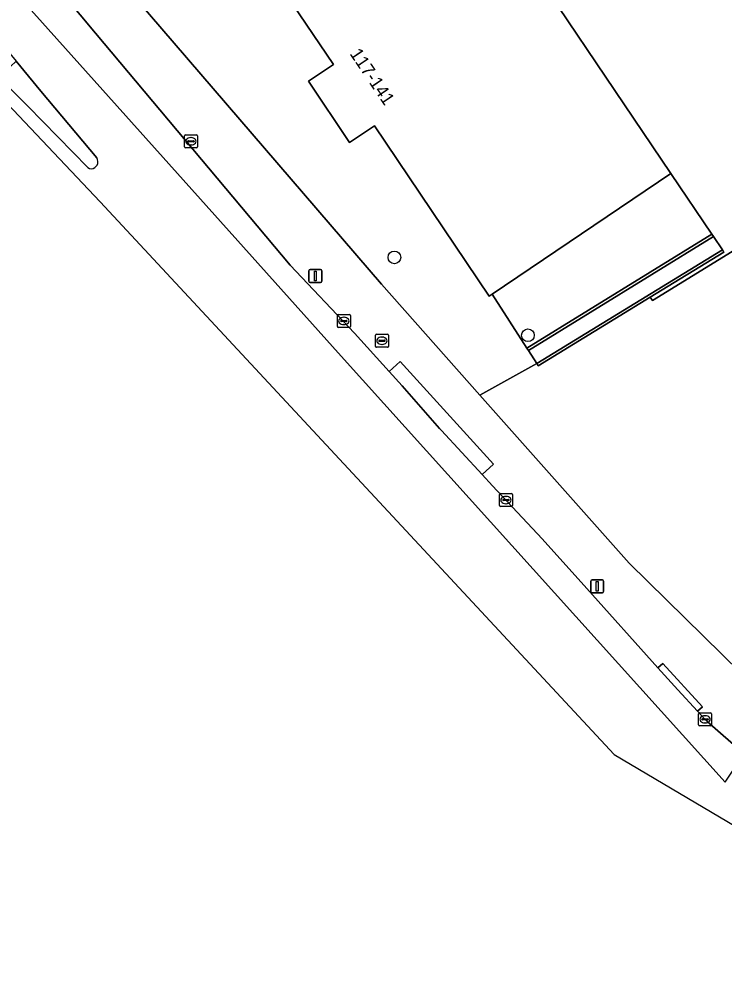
# Model space of a CAD drawing. Extents: x 161087 to 161926, y 382572 to 383873.
# Drawn here: x 161655.3 to 161709.7, y 382571.9 to 382644.9 of the extents above; entities that cross this region are included whole.
import ezdxf

# ---------------------------------------------------------------- set-up
doc = ezdxf.new("R2010")
doc.units = 0
for name, color, linetype in [('IMGEO_Boom', 7, 'Continuous'), ('IMGEO_Erf', 7, 'Continuous'), ('IMGEO_Kolk', 7, 'Continuous'), ('IMGEO_Lichtmast', 7, 'Continuous'), ('IMGEO_Muur', 7, 'Continuous'), ('IMGEO_Pand', 7, 'Continuous'), ('IMGEO_Pand_nummerreeks', 7, 'Continuous'), ('IMGEO_Rijbaan_lokaal_gesloten', 7, 'Continuous'), ('IMGEO_Rijbaan_lokaal_open', 7, 'Continuous'), ('IMGEO_Rioolput', 7, 'Continuous'), ('IMGEO_Verkeerseiland_open', 7, 'Continuous'), ('IMGEO_Voetpad_open', 7, 'Continuous')]:
    doc.layers.add(name, color=color, linetype=linetype)

msp = doc.modelspace()

# ---------------------------------------------------------------- linework, layer by layer
at = {"layer": 'IMGEO_Boom'}
for centre in [(161684.288, 382626.497), (161694.582, 382620.498)]:
    msp.add_circle(centre, 0.489, dxfattribs=at)
at = {"layer": 'IMGEO_Erf'}
for points in [[(161715.388, 382659.714), (161715.213, 382659.599), (161715.065, 382659.813), (161715.235, 382659.927), (161712.849, 382663.468), (161711.028, 382662.242), (161709.203, 382664.95), (161691.894, 382653.285), (161705.616, 382632.96), (161708.777, 382628.279), (161708.895, 382628.104), (161709.59, 382627.074), (161709.708, 382626.9), (161704.022, 382623.425), (161704.187, 382623.185), (161742.576, 382646.789), (161760.971, 382658.101), (161760.61, 382659.053), (161759.351, 382662.367), (161759.169, 382662.845), (161745.752, 382698.169)], [(161779.952, 382608.946), (161767.176, 382642.388), (161760.971, 382658.101), (161742.576, 382646.789), (161704.187, 382623.185), (161704.022, 382623.425), (161695.384, 382618.145), (161695.27, 382618.322), (161690.885, 382615.891), (161702.391, 382602.921), (161711.019, 382594.472), (161714.507, 382591.277)], [(161663.329, 382647.645), (161683.298, 382624.442), (161690.885, 382615.891), (161695.27, 382618.322), (161694.625, 382619.322), (161694.511, 382619.499), (161691.82, 382623.671), (161691.596, 382623.521), (161682.748, 382636.635), (161680.826, 382635.348), (161677.646, 382640.087), (161679.583, 382641.37), (161672.727, 382651.507)]]:
    msp.add_lwpolyline(points, dxfattribs=at)
at = {"layer": 'IMGEO_Kolk'}
for p, q in [((161668.089, 382635.023), (161668.089, 382635.875)), ((161668.164, 382635.949), (161669.016, 382635.949)), ((161669.09, 382635.875), (161669.09, 382635.023)), ((161668.348, 382635.443), (161668.348, 382635.455)), ((161668.786, 382635.406), (161668.388, 382635.406)), ((161668.391, 382635.492), (161668.789, 382635.492)), ((161668.6, 382635.169), (161668.575, 382635.169)), ((161668.577, 382635.729), (161668.602, 382635.729)), ((161668.832, 382635.455), (161668.832, 382635.443)), ((161669.016, 382634.949), (161668.164, 382634.949)), ((161679.885, 382621.176), (161679.885, 382622.028)), ((161679.96, 382622.102), (161680.812, 382622.102)), ((161680.886, 382622.028), (161680.886, 382621.176)), ((161680.144, 382621.596), (161680.144, 382621.608)), ((161680.582, 382621.559), (161680.184, 382621.559)), ((161680.187, 382621.645), (161680.585, 382621.645)), ((161680.396, 382621.322), (161680.371, 382621.322)), ((161680.373, 382621.882), (161680.398, 382621.882)), ((161680.628, 382621.608), (161680.628, 382621.596)), ((161680.812, 382621.102), (161679.96, 382621.102)), ((161692.389, 382607.365), (161692.389, 382608.217)), ((161692.464, 382608.291), (161693.316, 382608.291)), ((161693.39, 382608.217), (161693.39, 382607.365)), ((161692.648, 382607.785), (161692.648, 382607.797)), ((161693.086, 382607.748), (161692.688, 382607.748)), ((161692.691, 382607.834), (161693.089, 382607.834)), ((161692.9, 382607.511), (161692.875, 382607.511)), ((161692.877, 382608.071), (161692.902, 382608.071)), ((161693.132, 382607.797), (161693.132, 382607.785)), ((161693.316, 382607.291), (161692.464, 382607.291)), ((161707.83, 382591.39), (161708.682, 382591.39)), ((161707.755, 382590.464), (161707.755, 382591.316)), ((161708.014, 382590.884), (161708.014, 382590.896)), ((161708.452, 382590.847), (161708.054, 382590.847)), ((161708.057, 382590.933), (161708.455, 382590.933)), ((161708.266, 382590.61), (161708.241, 382590.61)), ((161708.243, 382591.17), (161708.268, 382591.17)), ((161708.498, 382590.896), (161708.498, 382590.884)), ((161708.756, 382591.316), (161708.756, 382590.464)), ((161708.682, 382590.39), (161707.83, 382590.39))]:
    msp.add_line(p, q, dxfattribs=at)
for points in [[(161668.089, 382635.023), (161668.089, 382635.875)], [(161668.164, 382635.949), (161669.016, 382635.949)], [(161669.09, 382635.875), (161669.09, 382635.023)], [(161669.016, 382634.949), (161668.164, 382634.949)], [(161679.885, 382621.176), (161679.885, 382622.028)], [(161679.96, 382622.102), (161680.812, 382622.102)], [(161680.886, 382622.028), (161680.886, 382621.176)], [(161680.812, 382621.102), (161679.96, 382621.102)], [(161692.389, 382607.365), (161692.389, 382608.217)], [(161692.464, 382608.291), (161693.316, 382608.291)], [(161693.39, 382608.217), (161693.39, 382607.365)], [(161693.316, 382607.291), (161692.464, 382607.291)], [(161707.83, 382591.39), (161708.682, 382591.39)], [(161707.755, 382590.464), (161707.755, 382591.316)], [(161708.756, 382591.316), (161708.756, 382590.464)], [(161708.682, 382590.39), (161707.83, 382590.39)]]:
    msp.add_lwpolyline(points, dxfattribs=at)
for centre, radius, start, end in [((161668.166, 382635.873), 0.0765, 91.55205, 178.44795), ((161668.166, 382635.873), 0.0765, 91.55205, 178.44795), ((161669.014, 382635.873), 0.0765, 1.55205, 88.44795), ((161669.014, 382635.873), 0.0765, 1.55205, 88.44795), ((161668.388, 382635.452), 0.0403, 85.87752, 175.75265), ((161668.385, 382635.442), 0.0366, 178.93798, 274.71019), ((161668.789, 382635.449), 0.043, 264.86636, 352.45326), ((161668.793, 382635.454), 0.0386, 1.73085, 96.63898), ((161668.166, 382635.025), 0.0765, 181.55205, 268.44795), ((161668.166, 382635.025), 0.0765, 181.55205, 268.44795), ((161669.014, 382635.025), 0.0765, 271.55205, 358.44795), ((161669.014, 382635.025), 0.0765, 271.55205, 358.44795), ((161679.962, 382622.026), 0.0765, 91.55205, 178.44795), ((161679.962, 382622.026), 0.0765, 91.55205, 178.44795), ((161680.81, 382622.026), 0.0765, 1.55205, 88.44795), ((161680.81, 382622.026), 0.0765, 1.55205, 88.44795), ((161680.184, 382621.605), 0.0403, 85.87752, 175.75265), ((161680.181, 382621.595), 0.0366, 178.93798, 274.71019), ((161680.585, 382621.602), 0.043, 264.86636, 352.45326), ((161680.589, 382621.607), 0.0386, 1.73085, 96.63898), ((161679.962, 382621.178), 0.0765, 181.55205, 268.44795), ((161679.962, 382621.178), 0.0765, 181.55205, 268.44795), ((161680.81, 382621.178), 0.0765, 271.55205, 358.44795), ((161680.81, 382621.178), 0.0765, 271.55205, 358.44795), ((161692.466, 382608.215), 0.0765, 91.55205, 178.44795), ((161692.466, 382608.215), 0.0765, 91.55205, 178.44795), ((161693.314, 382608.215), 0.0765, 1.55205, 88.44795), ((161693.314, 382608.215), 0.0765, 1.55205, 88.44795), ((161692.688, 382607.794), 0.0403, 85.87752, 175.75265), ((161692.685, 382607.784), 0.0366, 178.93798, 274.71019), ((161693.089, 382607.791), 0.043, 264.86636, 352.45326), ((161693.093, 382607.796), 0.0386, 1.73085, 96.63898), ((161692.466, 382607.367), 0.0765, 181.55205, 268.44795), ((161692.466, 382607.367), 0.0765, 181.55205, 268.44795), ((161693.314, 382607.367), 0.0765, 271.55205, 358.44795), ((161693.314, 382607.367), 0.0765, 271.55205, 358.44795), ((161707.832, 382591.314), 0.0765, 91.55205, 178.44795), ((161707.832, 382591.314), 0.0765, 91.55205, 178.44795), ((161708.68, 382591.314), 0.0765, 1.55205, 88.44795), ((161708.68, 382591.314), 0.0765, 1.55205, 88.44795), ((161708.054, 382590.893), 0.0403, 85.87752, 175.75265), ((161708.051, 382590.883), 0.0366, 178.93798, 274.71019), ((161708.455, 382590.89), 0.043, 264.86636, 352.45326), ((161708.459, 382590.895), 0.0386, 1.73085, 96.63898), ((161707.832, 382590.466), 0.0765, 181.55205, 268.44795), ((161707.832, 382590.466), 0.0765, 181.55205, 268.44795), ((161708.68, 382590.466), 0.0765, 271.55205, 358.44795), ((161708.68, 382590.466), 0.0765, 271.55205, 358.44795)]:
    msp.add_arc(centre, radius, start, end, dxfattribs=at)
for centre, major_axis, ratio, start_param, end_param in [((161668.576, 382635.449), (-0.387, 0.002), 0.722429, 4.712389, 7.853982), ((161668.601, 382635.449), (-0.39, 0.002), 0.717154, 1.570796, 4.712389), ((161680.372, 382621.602), (-0.387, 0.002), 0.722429, 4.712389, 7.853982), ((161680.397, 382621.602), (-0.39, 0.002), 0.717154, 1.570796, 4.712389), ((161692.876, 382607.791), (-0.387, 0.002), 0.722429, 4.712389, 7.853982), ((161692.901, 382607.791), (-0.39, 0.002), 0.717154, 1.570796, 4.712389), ((161708.242, 382590.89), (-0.387, 0.002), 0.722429, 4.712389, 7.853982), ((161708.267, 382590.89), (-0.39, 0.002), 0.717154, 1.570796, 4.712389)]:
    msp.add_ellipse(centre, major_axis=major_axis, ratio=ratio, start_param=start_param, end_param=end_param, dxfattribs=at)
at = {"layer": 'IMGEO_Lichtmast'}
for p, q in [((161677.69, 382624.661), (161677.69, 382625.461)), ((161677.69, 382625.461), (161677.69, 382624.661)), ((161677.79, 382625.561), (161678.58, 382625.561)), ((161678.58, 382625.561), (161677.79, 382625.561)), ((161678.68, 382625.461), (161678.68, 382624.661)), ((161678.68, 382624.661), (161678.68, 382625.461)), ((161678.58, 382624.561), (161677.79, 382624.561)), ((161677.79, 382624.561), (161678.58, 382624.561)), ((161699.539, 382601.641), (161700.329, 382601.641)), ((161700.329, 382601.641), (161699.539, 382601.641)), ((161699.439, 382600.741), (161699.439, 382601.541)), ((161699.439, 382601.541), (161699.439, 382600.741)), ((161700.429, 382601.541), (161700.429, 382600.741)), ((161700.429, 382600.741), (161700.429, 382601.541)), ((161700.329, 382600.641), (161699.539, 382600.641)), ((161699.539, 382600.641), (161700.329, 382600.641))]:
    msp.add_line(p, q, dxfattribs=at)
for points in [[(161678.11, 382625.436), (161678.26, 382625.436), (161678.26, 382624.686), (161678.11, 382624.686), (161678.11, 382625.436)], [(161699.859, 382601.516), (161700.009, 382601.516), (161700.009, 382600.766), (161699.859, 382600.766), (161699.859, 382601.516)]]:
    msp.add_lwpolyline(points, dxfattribs=at)
for centre, start, end in [((161677.79, 382625.461), 90, 180), ((161677.79, 382625.461), 90, 180), ((161678.58, 382625.461), 0, 90), ((161678.58, 382625.461), 360, 90), ((161677.79, 382624.661), 180, 270), ((161677.79, 382624.661), 180, 270), ((161678.58, 382624.661), 270, 0), ((161678.58, 382624.661), 270, 0), ((161699.539, 382601.541), 90, 180), ((161699.539, 382601.541), 90, 180), ((161700.329, 382601.541), 0, 90), ((161700.329, 382601.541), 360, 90), ((161699.539, 382600.741), 180, 270), ((161699.539, 382600.741), 180, 270), ((161700.329, 382600.741), 270, 0), ((161700.329, 382600.741), 270, 0)]:
    msp.add_arc(centre, 0.1, start, end, dxfattribs=at)
at = {"layer": 'IMGEO_Muur'}
for points in [[(161708.895, 382628.104), (161708.777, 382628.279), (161694.511, 382619.499), (161694.625, 382619.322)], [(161709.708, 382626.9), (161709.59, 382627.074), (161695.27, 382618.322), (161695.384, 382618.145), (161704.022, 382623.425)]]:
    msp.add_lwpolyline(points, close=True, dxfattribs=at)
at = {"layer": 'IMGEO_Pand'}
msp.add_lwpolyline([(161672.727, 382651.507), (161679.583, 382641.37), (161677.646, 382640.087), (161680.826, 382635.348), (161682.748, 382636.635), (161691.596, 382623.521), (161691.82, 382623.671), (161705.616, 382632.96), (161691.894, 382653.285)], dxfattribs=at)
at = {"layer": 'IMGEO_Rijbaan_lokaal_gesloten'}
for points in [[(161563.602, 382736.77), (161592.087, 382705.487), (161622.627, 382671.947), (161661.586, 382630.771), (161701.238, 382588.176), (161728.827, 382571.874), (161779.525, 382578.285), (161779.123, 382582.55), (161766.2, 382581.371), (161761.033, 382580.909)], [(161709.816, 382586.053), (161680.185, 382618.886), (161643.825, 382659.427), (161627.635, 382677.479), (161586.909, 382721.287), (161583.729, 382724.844), (161582.233, 382726.427)], [(161643.825, 382659.427), (161680.185, 382618.886), (161709.816, 382586.053), (161711.27, 382588.243), (161708.423, 382590.72), (161708.255, 382590.889), (161707.678, 382591.51), (161706.14, 382593.165), (161704.614, 382594.867), (161699.125, 382600.989), (161695.676, 382604.795), (161691.858, 382608.899), (161691.059, 382609.76), (161687.909, 382613.153), (161687.765, 382613.317), (161684.88, 382616.608), (161683.888, 382617.699), (161681.202, 382620.653), (161676.251, 382625.901), (161661.238, 382643.793), (161658.863, 382646.624), (161658.558, 382647.024), (161645.804, 382661.238)], [(161652.483, 382644.753), (161652.586, 382644.632), (161655.093, 382641.612), (161657.007, 382639.307), (161661.318, 382634.17)], [(161660.643, 382633.418), (161656.005, 382638.153), (161653.864, 382640.289), (161653.771, 382640.396), (161651.127, 382643.442)], [(161661.352, 382633.604), (161661.178, 382633.418)]]:
    msp.add_lwpolyline(points, dxfattribs=at)
for centre, radius, start, end in [((161660.782, 382633.854), 0.622, 336.33806, 30.53727), ((161660.91, 382633.767), 0.439, 232.50163, 307.49837)]:
    msp.add_arc(centre, radius, start, end, dxfattribs=at)
at = {"layer": 'IMGEO_Rijbaan_lokaal_open'}
msp.add_lwpolyline([(161708.777, 382628.279), (161705.616, 382632.96), (161691.82, 382623.671), (161694.511, 382619.499)], close=True, dxfattribs=at)
at = {"layer": 'IMGEO_Rioolput'}
for p, q in [((161682.899, 382620.569), (161683.751, 382620.569)), ((161682.824, 382619.643), (161682.824, 382620.495)), ((161683.083, 382620.063), (161683.083, 382620.075)), ((161683.521, 382620.026), (161683.123, 382620.026)), ((161683.126, 382620.112), (161683.524, 382620.112)), ((161683.312, 382620.349), (161683.337, 382620.349)), ((161683.567, 382620.075), (161683.567, 382620.063)), ((161683.825, 382620.495), (161683.825, 382619.643)), ((161683.751, 382619.569), (161682.899, 382619.569)), ((161683.335, 382619.789), (161683.31, 382619.789))]:
    msp.add_line(p, q, dxfattribs=at)
for points in [[(161682.899, 382620.569), (161683.751, 382620.569)], [(161682.824, 382619.643), (161682.824, 382620.495)], [(161683.825, 382620.495), (161683.825, 382619.643)], [(161683.751, 382619.569), (161682.899, 382619.569)]]:
    msp.add_lwpolyline(points, dxfattribs=at)
for centre, radius, start, end in [((161682.901, 382620.493), 0.0765, 91.55205, 178.44795), ((161682.901, 382620.493), 0.0765, 91.55205, 178.44795), ((161683.749, 382620.493), 0.0765, 1.55205, 88.44795), ((161683.749, 382620.493), 0.0765, 1.55205, 88.44795), ((161683.123, 382620.072), 0.0403, 85.87752, 175.75265), ((161683.12, 382620.062), 0.0366, 178.93798, 274.71019), ((161683.524, 382620.069), 0.043, 264.86636, 352.45326), ((161683.528, 382620.074), 0.0386, 1.73085, 96.63898), ((161682.901, 382619.645), 0.0765, 181.55205, 268.44795), ((161682.901, 382619.645), 0.0765, 181.55205, 268.44795), ((161683.749, 382619.645), 0.0765, 271.55205, 358.44795), ((161683.749, 382619.645), 0.0765, 271.55205, 358.44795)]:
    msp.add_arc(centre, radius, start, end, dxfattribs=at)
for centre, major_axis, ratio, start_param, end_param in [((161683.311, 382620.069), (-0.387, 0.002), 0.722429, 4.712389, 7.853982), ((161683.336, 382620.069), (-0.39, 0.002), 0.717154, 1.570796, 4.712389)]:
    msp.add_ellipse(centre, major_axis=major_axis, ratio=ratio, start_param=start_param, end_param=end_param, dxfattribs=at)
at = {"layer": 'IMGEO_Verkeerseiland_open'}
for points in [[(161655.093, 382641.612), (161653.771, 382640.396), (161653.864, 382640.289), (161656.005, 382638.153), (161660.643, 382633.418)], [(161661.318, 382634.17), (161657.007, 382639.307), (161655.093, 382641.612)], [(161661.178, 382633.418), (161661.352, 382633.604)]]:
    msp.add_lwpolyline(points, dxfattribs=at)
for centre, radius, start, end in [((161660.782, 382633.854), 0.622, 336.33806, 30.53727), ((161660.91, 382633.767), 0.439, 232.50163, 307.49837)]:
    msp.add_arc(centre, radius, start, end, dxfattribs=at)
at = {"layer": 'IMGEO_Voetpad_open'}
for points in [[(161683.298, 382624.442), (161663.329, 382647.645), (161658.141, 382653.069)], [(161658.558, 382647.024), (161658.863, 382646.624), (161661.238, 382643.793), (161676.251, 382625.901), (161681.202, 382620.653), (161683.888, 382617.699), (161684.741, 382618.476), (161691.942, 382610.568), (161691.059, 382609.76), (161691.858, 382608.899), (161695.676, 382604.795), (161699.125, 382600.989), (161704.614, 382594.867), (161704.983, 382595.204), (161708.047, 382591.847), (161707.678, 382591.51), (161708.255, 382590.889), (161708.423, 382590.72), (161711.27, 382588.243), (161711.463, 382588.091)], [(161714.507, 382591.277), (161711.019, 382594.472), (161702.391, 382602.921), (161690.885, 382615.891), (161683.298, 382624.442)]]:
    msp.add_lwpolyline(points, dxfattribs=at)
for points in [[(161709.59, 382627.074), (161708.895, 382628.104), (161694.625, 382619.322), (161695.27, 382618.322)], [(161683.888, 382617.699), (161684.88, 382616.608), (161687.765, 382613.317), (161687.909, 382613.153), (161691.059, 382609.76), (161691.942, 382610.568), (161684.741, 382618.476)], [(161707.678, 382591.51), (161708.047, 382591.847), (161704.983, 382595.204), (161704.614, 382594.867), (161706.14, 382593.165)]]:
    msp.add_lwpolyline(points, close=True, dxfattribs=at)

# ---------------------------------------------------------------- texts
at = {"layer": 'IMGEO_Pand_nummerreeks'}
msp.add_text('117-141', height=1, rotation=304.00483, dxfattribs=at).set_placement((161680.802, 382642.201))

doc.saveas('drawing.dxf')
